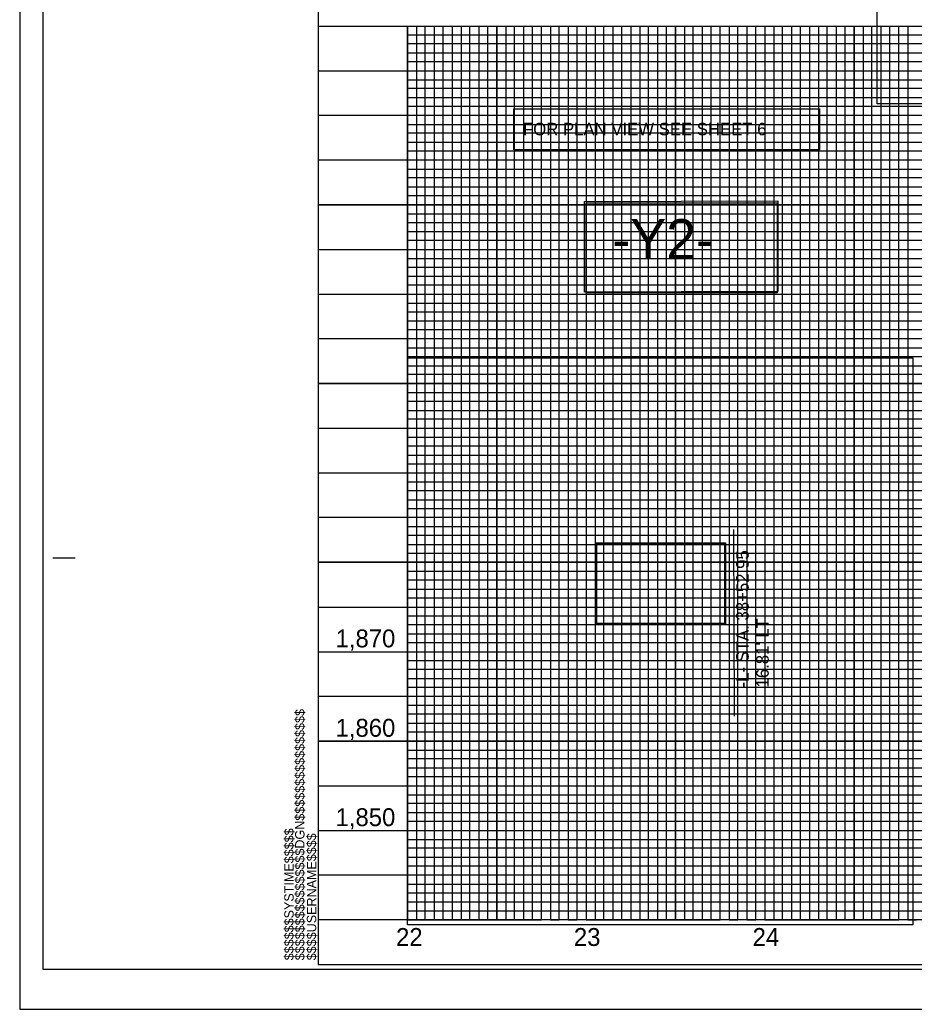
# Model space of a CAD drawing. Extents: x 557032 to 558930, y 525869 to 527437.
# Drawn here: x 557032 to 557533, y 525869 to 526423 of the extents above; entities that cross this region are included whole.
import ezdxf

# ---------------------------------------------------------------- set-up
doc = ezdxf.new("R2010")
doc.units = 0
for name, color, linetype in [('Exist Vertical Profile Horizontal Axis Label Major', 7, 'Continuous'), ('Exist Vertical Profile Vertical Axis Label', 7, 'Continuous'), ('Prop Vertical Profile Curve Label', 7, 'Continuous'), ('Prop Vertical Profile Grade Label', 7, 'Continuous'), ('Prop VPI Label', 7, 'Continuous'), ('Raster_Level_4', 7, 'Continuous'), ('Sheet Cutting Line CELL', 7, 'Continuous'), ('Sheet DOT Grid CELL', 7, 'Continuous'), ('Sheet Layout Profile Border Port 2', 7, 'Continuous'), ('Sheet Plot Border Inside CELL', 7, 'Continuous'), ('Sheet Plot Border Outside CELL', 7, 'Continuous'), ('Sheet Profile CELL', 7, 'Continuous'), ('Sheet Profile Grid Major CELL', 7, 'Continuous'), ('Sheet Profile Grid Middle CELL', 7, 'Continuous'), ('Sheet Profile Grid Minor CELL', 7, 'Continuous')]:
    doc.layers.add(name, color=color, linetype=linetype)

msp = doc.modelspace()

# ---------------------------------------------------------------- linework, layer by layer
at = {"layer": 'Prop Vertical Profile Curve Label'}
for points in [[(557349.44, 526320.27), (557456.33, 526320.27), (557456.33, 526269.93), (557349.44, 526269.93)], [(557355.39, 526129.86), (557426.92, 526129.86), (557426.92, 526085.02), (557355.39, 526085.02)]]:
    msp.add_lwpolyline(points, close=True, dxfattribs=at)
at = {"layer": 'Prop VPI Label'}
msp.add_line((557432.51, 526033.12), (557432.16, 526137.66), dxfattribs=at)
for points in [[(557308.98, 526372.92), (557480.12, 526372.92), (557480.12, 526350), (557308.98, 526350)], [(557308.98, 526372.92), (557480.12, 526372.92), (557480.12, 526350), (557308.98, 526350)], [(557348.62, 526321.01), (557456.85, 526321.46), (557456.85, 526270.73), (557348.62, 526270.28)], [(557354.99, 526130.16), (557427.42, 526130.16), (557427.42, 526084.64), (557354.99, 526084.64)]]:
    msp.add_lwpolyline(points, close=True, dxfattribs=at)
at = {"layer": 'Raster_Level_4'}
for points in [[(557512.44, 526788.54), (557922.28, 526788.54), (557922.28, 526375.72), (557512.44, 526375.72)], [(557249.46, 526233.7), (557532.35, 526233.7), (557532.35, 525916.46), (557249.46, 525916.46)]]:
    msp.add_lwpolyline(points, close=True, dxfattribs=at)
at = {"layer": 'Sheet Cutting Line CELL'}
for p, q in [((557032.45, 526969.22), (557032.45, 525869.22)), ((557032.45, 525869.22), (558716.45, 525869.22))]:
    msp.add_line(p, q, dxfattribs=at)
at = {"layer": 'Sheet DOT Grid CELL'}
for p, q in [((557199.45, 526419.22), (558699.34, 526419.22)), ((557249.45, 526419.22), (557249.45, 525919.22)), ((557299.45, 526419.22), (557299.45, 525919.22)), ((557349.45, 526419.22), (557349.45, 525919.22)), ((557399.45, 526419.22), (557399.45, 525919.22)), ((557449.45, 526419.22), (557449.45, 525919.22)), ((557499.45, 526419.22), (557499.45, 525919.22)), ((557199.45, 526319.22), (558699.34, 526319.22)), ((557199.45, 526269.22), (558699.34, 526269.22)), ((557199.45, 526219.22), (558699.34, 526219.22)), ((557199.45, 526169.22), (558699.34, 526169.22)), ((557199.45, 526119.22), (558699.34, 526119.22)), ((557199.45, 526069.22), (558699.34, 526069.22)), ((557199.45, 526019.22), (558699.34, 526019.22)), ((557199.45, 525969.22), (558699.34, 525969.22))]:
    msp.add_line(p, q, dxfattribs=at)
at = {"layer": 'Sheet Layout Profile Border Port 2'}
msp.add_lwpolyline([(557249.45, 526419.22), (558649.45, 526419.22), (558649.45, 525919.22), (557249.45, 525919.22)], close=True, dxfattribs=at)
at = {"layer": 'Sheet Plot Border Inside CELL'}
msp.add_lwpolyline([(557045.45, 525891.67), (558711.95, 525891.67), (558711.95, 526946.77), (557045.45, 526946.77)], close=True, dxfattribs=at)
at = {"layer": 'Sheet Plot Border Outside CELL'}
msp.add_lwpolyline([(557032.45, 525869.22), (558716.45, 525869.22), (558716.45, 526969.22), (557032.45, 526969.22)], close=True, dxfattribs=at)
at = {"layer": 'Sheet Profile CELL'}
for p, q in [((557199.45, 526419.22), (558699.45, 526419.22)), ((557050.95, 526121.72), (557063.45, 526121.72)), ((558699.45, 525919.22), (557199.45, 525919.22)), ((557199.45, 525894.22), (558699.45, 525894.22)), ((557199.45, 525894.22), (557199.45, 525894.22)), ((557199.45, 525894.22), (557199.45, 525894.22)), ((557199.45, 525894.22), (557199.45, 525894.22)), ((557199.45, 525894.22), (557199.45, 525894.22)), ((557199.45, 525894.22), (557199.45, 525894.22)), ((557199.45, 525894.22), (557199.45, 525894.22)), ((557199.45, 525894.22), (557199.45, 525894.22))]:
    msp.add_line(p, q, dxfattribs=at)
msp.add_lwpolyline([(558699.45, 526944.22), (557199.45, 526944.22), (557199.45, 525894.22), (558699.45, 525894.22)], close=True, dxfattribs=at)
msp.add_lwpolyline([(557236.95, 525894.22), (557236.95, 525894.22)], dxfattribs=at)
at = {"layer": 'Sheet Profile Grid Major CELL'}
msp.add_line((557199.45, 525919.22), (557199.45, 525919.22), dxfattribs=at)
for points in [[(557249.45, 526419.22), (557249.45, 525919.22), (557299.45, 525919.22), (557299.45, 526419.22), (557349.45, 526419.22), (557349.45, 525919.22), (557399.45, 525919.22), (557399.45, 526419.22), (557449.45, 526419.22), (557449.45, 525919.22), (557499.45, 525919.22), (557499.45, 526419.22), (557549.45, 526419.22)], [(558699.45, 526369.22), (557199.45, 526369.22)], [(558699.45, 526319.22), (557199.45, 526319.22), (557199.45, 526269.22), (558699.45, 526269.22)], [(558699.45, 526219.22), (557199.45, 526219.22), (557199.45, 526169.22), (558699.45, 526169.22)], [(558699.45, 526119.22), (557199.45, 526119.22), (557199.45, 526069.22), (558699.45, 526069.22)], [(558542.78, 526019.22), (557199.45, 526019.22), (557199.45, 526019.22), (557199.45, 525969.22), (558699.45, 525969.22)], [(558699.45, 525919.22), (557199.45, 525919.22)]]:
    msp.add_lwpolyline(points, dxfattribs=at)
at = {"layer": 'Sheet Profile Grid Middle CELL'}
for points in [[(557224.45, 526419.22), (557274.45, 526419.22), (557274.45, 525919.22), (557324.45, 525919.22), (557324.45, 526419.22), (557374.45, 526419.22), (557374.45, 525919.22), (557424.45, 525919.22), (557424.45, 526419.22), (557474.45, 526419.22), (557474.45, 525919.22), (557524.45, 525919.22), (557524.45, 526419.22), (557574.45, 526419.22)], [(557199.45, 526394.22), (558699.45, 526394.22)], [(558699.45, 526344.22), (557199.45, 526344.22), (557199.45, 526294.22), (558699.45, 526294.22)], [(558699.45, 526244.22), (557199.45, 526244.22), (557199.45, 526194.22), (558699.45, 526194.22)], [(558699.45, 526144.22), (557199.45, 526144.22), (557199.45, 526094.22), (558699.45, 526094.22)], [(558699.45, 526044.22), (557199.45, 526044.22), (557199.45, 525994.22), (558699.45, 525994.22)], [(558699.45, 525944.22), (557199.45, 525944.22)]]:
    msp.add_lwpolyline(points, dxfattribs=at)
at = {"layer": 'Sheet Profile Grid Minor CELL'}
for p, q in [((557249.45, 526419.22), (557254.45, 526419.22)), ((557254.45, 526419.22), (557254.45, 525919.22)), ((557259.45, 525919.22), (557259.45, 526419.22)), ((557259.45, 526419.22), (557264.45, 526419.22)), ((557264.45, 526419.22), (557264.45, 525919.22)), ((557269.45, 525919.22), (557269.45, 526419.22)), ((557269.45, 526419.22), (557279.45, 526419.22)), ((557279.45, 526419.22), (557279.45, 525919.22)), ((557284.45, 525919.22), (557284.45, 526419.22)), ((557284.45, 526419.22), (557289.45, 526419.22)), ((557289.45, 526419.22), (557289.45, 525919.22)), ((557309.45, 525919.22), (557309.45, 526419.22)), ((557309.45, 526419.22), (557314.45, 526419.22)), ((557314.45, 526419.22), (557314.45, 525919.22)), ((557319.45, 525919.22), (557319.45, 526419.22)), ((557319.45, 526419.22), (557329.45, 526419.22)), ((557329.45, 526419.22), (557329.45, 525919.22)), ((557334.45, 525919.22), (557334.45, 526419.22)), ((557334.45, 526419.22), (557339.45, 526419.22)), ((557339.45, 526419.22), (557339.45, 525919.22)), ((557344.45, 525919.22), (557344.45, 526419.22)), ((557344.45, 526419.22), (557354.45, 526419.22)), ((557354.45, 526419.22), (557354.45, 525919.22)), ((557359.45, 525919.22), (557359.45, 526419.22)), ((557359.45, 526419.22), (557364.45, 526419.22)), ((557364.45, 526419.22), (557364.45, 525919.22)), ((557369.45, 525919.22), (557369.45, 526419.22)), ((557369.45, 526419.22), (557379.45, 526419.22)), ((557379.45, 526419.22), (557379.45, 525919.22)), ((557384.45, 525919.22), (557384.45, 526419.22)), ((557384.45, 526419.22), (557389.45, 526419.22)), ((557389.45, 526419.22), (557389.45, 525919.22)), ((557394.45, 525919.22), (557394.45, 526419.22)), ((557394.45, 526419.22), (557404.45, 526419.22)), ((557404.45, 526419.22), (557404.45, 525919.22)), ((557409.45, 525919.22), (557409.45, 526419.22)), ((557409.45, 526419.22), (557414.45, 526419.22)), ((557414.45, 526419.22), (557414.45, 525919.22)), ((557419.45, 525919.22), (557419.45, 526419.22)), ((557419.45, 526419.22), (557429.45, 526419.22)), ((557429.45, 526419.22), (557429.45, 525919.22)), ((557434.45, 525919.22), (557434.45, 526419.22)), ((557434.45, 526419.22), (557439.45, 526419.22)), ((557439.45, 526419.22), (557439.45, 525919.22)), ((557444.45, 525919.22), (557444.45, 526419.22)), ((557444.45, 526419.22), (557454.45, 526419.22)), ((557454.45, 526419.22), (557454.45, 525919.22)), ((557459.45, 525919.22), (557459.45, 526419.22)), ((557459.45, 526419.22), (557464.45, 526419.22)), ((557464.45, 526419.22), (557464.45, 525919.22)), ((557249.45, 526414.22), (558649.45, 526414.22)), ((558649.45, 526409.22), (557249.45, 526409.22)), ((557249.45, 526404.22), (558649.45, 526404.22)), ((558649.45, 526399.22), (557249.45, 526399.22)), ((557249.45, 526389.22), (558649.45, 526389.22)), ((558649.45, 526384.22), (557249.45, 526384.22)), ((557249.45, 526379.22), (558649.45, 526379.22)), ((558649.45, 526374.22), (557249.45, 526374.22)), ((557249.45, 526364.22), (558649.45, 526364.22)), ((558649.45, 526359.22), (557249.45, 526359.22)), ((557249.45, 526354.22), (558649.45, 526354.22)), ((558649.45, 526349.22), (557249.45, 526349.22)), ((557249.45, 526339.22), (558649.45, 526339.22)), ((558649.45, 526334.22), (557249.45, 526334.22)), ((557249.45, 526329.22), (558649.45, 526329.22)), ((558649.45, 526324.22), (557249.45, 526324.22)), ((557249.45, 526314.22), (558649.45, 526314.22)), ((558649.45, 526309.22), (557249.45, 526309.22)), ((557249.45, 526304.22), (558649.45, 526304.22)), ((558649.45, 526299.22), (557249.45, 526299.22)), ((557249.45, 526289.22), (558649.45, 526289.22)), ((558649.45, 526284.22), (557249.45, 526284.22)), ((557249.45, 526279.22), (558649.45, 526279.22)), ((558649.45, 526274.22), (557249.45, 526274.22)), ((557249.45, 526264.22), (558649.45, 526264.22)), ((558649.45, 526259.22), (557249.45, 526259.22)), ((557249.45, 526254.22), (558649.45, 526254.22)), ((558649.45, 526249.22), (557249.45, 526249.22)), ((557249.45, 526239.22), (558649.45, 526239.22)), ((558649.45, 526234.22), (557249.45, 526234.22)), ((557249.45, 526229.22), (558649.45, 526229.22)), ((558649.45, 526224.22), (557249.45, 526224.37)), ((557249.45, 526214.22), (558649.45, 526214.22)), ((558649.45, 526209.22), (557249.45, 526209.22)), ((557249.45, 526204.22), (558649.45, 526204.22)), ((558649.45, 526199.22), (557249.45, 526199.22)), ((557249.45, 526189.22), (558649.45, 526189.22)), ((558649.45, 526184.22), (557249.45, 526184.22)), ((557249.45, 526179.22), (558649.45, 526179.22)), ((558649.45, 526174.22), (557249.45, 526174.22)), ((557249.45, 526164.22), (558649.45, 526164.22)), ((558649.45, 526159.22), (557249.45, 526159.22)), ((557249.45, 526154.22), (558649.45, 526154.22)), ((558649.45, 526149.22), (557249.45, 526149.22)), ((557249.45, 526139.22), (558649.45, 526139.22)), ((558649.45, 526134.22), (557249.45, 526134.22)), ((557249.45, 526129.22), (558649.45, 526129.22)), ((558649.45, 526124.22), (557249.45, 526124.22)), ((557249.45, 526114.22), (558649.45, 526114.22)), ((558649.45, 526109.22), (557249.45, 526109.22)), ((557249.45, 526104.22), (558649.45, 526104.22)), ((558649.45, 526099.22), (557249.45, 526099.22)), ((557249.45, 526089.22), (558649.45, 526089.22)), ((558649.45, 526084.22), (557249.45, 526084.22)), ((557249.45, 526079.22), (558649.45, 526079.22)), ((558649.45, 526074.22), (557249.45, 526074.22)), ((557249.45, 526064.22), (558649.45, 526064.22)), ((558649.45, 526059.22), (557249.45, 526059.22)), ((557249.45, 526054.22), (558649.45, 526054.22)), ((558649.45, 526049.22), (557249.45, 526049.22)), ((557249.45, 526039.22), (558542.78, 526039.22)), ((558542.78, 526034.22), (557249.45, 526034.22)), ((557249.45, 526029.22), (558542.78, 526029.22)), ((558542.78, 526024.22), (557249.45, 526024.22)), ((557249.45, 526014.22), (558649.45, 526014.22)), ((558649.45, 526009.22), (557249.45, 526009.22)), ((557249.45, 526004.22), (558649.45, 526004.22)), ((558649.45, 525999.22), (557249.45, 525999.22)), ((557249.45, 525989.22), (558649.45, 525989.22)), ((558649.45, 525984.22), (557249.45, 525984.22)), ((557249.45, 525979.22), (558649.45, 525979.22)), ((558649.45, 525974.22), (557249.45, 525974.22)), ((557249.45, 525964.22), (558649.45, 525964.22)), ((558649.45, 525959.22), (557249.45, 525959.22)), ((557249.45, 525954.22), (558649.45, 525954.22)), ((558649.45, 525949.22), (557249.45, 525949.22)), ((557249.45, 525939.22), (558649.45, 525939.22)), ((558649.45, 525934.22), (557249.45, 525934.22)), ((557249.45, 525929.22), (558649.45, 525929.22)), ((557249.45, 525924.22), (558649.45, 525924.22)), ((557254.45, 525919.22), (557259.45, 525919.22)), ((557264.45, 525919.22), (557269.45, 525919.22)), ((557279.45, 525919.22), (557284.45, 525919.22)), ((557289.45, 525919.22), (557294.45, 525919.22)), ((557294.45, 525919.22), (557304.45, 525919.22)), ((557304.45, 525919.22), (557309.45, 525919.22)), ((557314.45, 525919.22), (557319.45, 525919.22)), ((557329.45, 525919.22), (557334.45, 525919.22)), ((557339.45, 525919.22), (557344.45, 525919.22)), ((557354.45, 525919.22), (557359.45, 525919.22)), ((557364.45, 525919.22), (557369.45, 525919.22)), ((557379.45, 525919.22), (557384.45, 525919.22)), ((557389.45, 525919.22), (557394.45, 525919.22)), ((557404.45, 525919.22), (557409.45, 525919.22)), ((557414.45, 525919.22), (557419.45, 525919.22)), ((557429.45, 525919.22), (557434.45, 525919.22)), ((557439.45, 525919.22), (557444.45, 525919.22)), ((557454.45, 525919.22), (557459.45, 525919.22))]:
    msp.add_line(p, q, dxfattribs=at)
for points in [[(557294.45, 525919.22), (557294.45, 526419.22), (557304.45, 526419.22), (557304.45, 525919.22)], [(557464.45, 525919.22), (557469.45, 525919.22), (557469.45, 526419.22), (557479.45, 526419.22), (557479.45, 525919.22), (557484.45, 525919.22), (557484.45, 526419.22), (557489.45, 526419.22), (557489.45, 525919.22), (557494.45, 525919.22), (557494.45, 526419.22), (557504.45, 526419.22), (557504.45, 525919.22), (557509.45, 525919.22), (557509.45, 526419.22), (557514.45, 526419.22), (557514.45, 525919.22), (557519.45, 525919.22), (557519.45, 526419.22), (557529.45, 526419.22), (557529.45, 525919.22), (557534.45, 525919.22)]]:
    msp.add_lwpolyline(points, dxfattribs=at)

# ---------------------------------------------------------------- texts
at = {"layer": 'Exist Vertical Profile Horizontal Axis Label Major'}
for s, p in [('22', (557243.08, 525904.62)), ('23', (557342.62, 525904.62)), ('24', (557442.66, 525904.62))]:
    msp.add_text(s, height=10, dxfattribs=at).set_placement(p)
at = {"layer": 'Exist Vertical Profile Vertical Axis Label'}
for s, p in [('1,870', (557209.21, 526071.64)), ('1,860', (557209.21, 526021.64)), ('1,850', (557209.21, 525971.64))]:
    msp.add_text(s, height=10, dxfattribs=at).set_placement(p)
at = {"layer": 'Prop Vertical Profile Grade Label'}
msp.add_text('-Y2-', height=22.5, dxfattribs=at).set_placement((557364.16, 526288.69))
at = {"layer": 'Prop VPI Label'}
msp.add_text('FOR PLAN VIEW SEE SHEET 6', height=7, dxfattribs=at).set_placement((557314.14, 526358.08))
for s, p in [('-L- STA. 38+52.95', (557440.46, 526049.22)), ("16.81' LT", (557451.66, 526049.22))]:
    msp.add_text(s, height=7, rotation=90, dxfattribs=at).set_placement(p)
at = {"layer": 'Sheet Profile CELL'}
for s, p in [('$$$$$$$$$$$$$$$$DGN$$$$$$$$$$$$$$$$', (557191.82, 525896.6)), ('$$$$$$SYSTIME$$$$$', (557185.77, 525896.6)), ('$$$$USERNAME$$$$', (557198.39, 525896.61))]:
    msp.add_text(s, height=5.25, rotation=90, dxfattribs=at).set_placement(p)

doc.saveas('drawing.dxf')
